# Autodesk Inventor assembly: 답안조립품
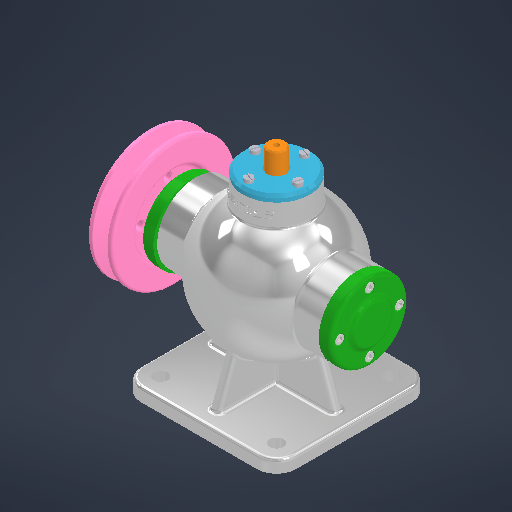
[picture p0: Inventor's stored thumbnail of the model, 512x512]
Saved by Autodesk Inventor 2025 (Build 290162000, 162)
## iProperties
Created: 2025-08
Part Number: 답안조립품
Document SubType Name: Assembly
Designer: infra005
Author: infra005
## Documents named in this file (15)
- C:\Users\infra005\Desktop\750807V1013\답안조립품.iam
- C:\Users\infra005\Desktop\750807V1013\V-벨트풀리\V-벨트풀리.ipt
- C:\Users\infra005\Desktop\750807V1013\너트 M8\너트 M8.ipt
- C:\Users\infra005\Desktop\750807V1013\뒤커버\뒤커버.ipt
- C:\Users\infra005\Desktop\750807V1013\베어링- 6202\베어링- 6202.ipt
- C:\Users\infra005\Desktop\750807V1013\볼트 M4 x 12\볼트 M4 x 12.ipt
- C:\Users\infra005\Desktop\750807V1013\볼트 M4 x 16\볼트 M4 x 16.ipt
- C:\Users\infra005\Desktop\750807V1013\상부커버\상부커버.ipt
- C:\Users\infra005\Desktop\750807V1013\슬라이드\슬라이드.ipt
- C:\Users\infra005\Desktop\750807V1013\앞커버\앞커버.ipt
- C:\Users\infra005\Desktop\750807V1013\오일실 15 30 7\오일실 15 30 7.ipt
- C:\Users\infra005\Desktop\750807V1013\칼라\칼라.ipt
- C:\Users\infra005\Desktop\750807V1013\키 4 x 4 x 12\키 4 x 4 x 12.ipt
- C:\Users\infra005\Desktop\750807V1013\편심축\편심축.ipt
- C:\Users\infra005\Desktop\750807V1013\본체.ipt
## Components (1 placed, 1 different names)
1. V-벨트풀리:1
